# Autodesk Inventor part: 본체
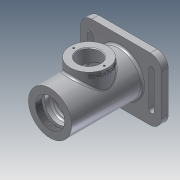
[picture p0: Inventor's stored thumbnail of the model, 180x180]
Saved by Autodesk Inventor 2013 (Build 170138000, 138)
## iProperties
Created: 2021-07
Part Number: 본체
Material: 알루미늄 6061
Document SubType Name: Modeling
Designer: user
Density: 2.71 g/cm^3
Mass: 738.277 g
Surface Area: 645 cm^2
Volume: 272.427 cm^3
Author: user
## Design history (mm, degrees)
sketch "스케치1"
  geometry: C1 r 31 at (0, 0); 1 further point
  constraints: 1 centre point, 1 coincident
  dimensions: "d0" = 62 diameter of C1
extrude "돌출1" new body sketch "스케치1" distance "d1" = 115; taper "d2" = 0 deg
node "작업 평면1"
sketch "스케치2"
  geometry: L1 (-58, 45)-(58, 45); L2 (58, 45)-(58, -45); L3 (58, -45)-(-58, -45); L4 (-58, -45)-(-58, 45); L5 (-58, 45)-(58, -45); L6 (58, 45)-(-58, -45); 1 further point
  constraints: 12 end point, 2 midpoint, 2 parallel, 1 horizontal, 1 perpendicular
  dimensions: "d4" = 116 distance of L2.end L3.end; "d5" = 90 distance of L1.end L2.end
extrude "돌출2" join sketch "스케치2" distance "d6" = 10; taper "d7" = 0 deg
sketch "스케치3"
  geometry: C1 r 31 at (0, 0) reference; C2 r 35 at (0, 0)
  constraints: 1 centre point, 1 coincident
  dimensions: "d8" = 70 diameter of C2
extrude "돌출3" join sketch "스케치3" distance "d9" = 3; taper "d10" = 0 deg
node "작업 평면2"
sketch "스케치5"
  geometry: L1 (31, 115)-(-31, 115) reference; L2 (35, 0)-(-35, 0) reference; L3 (0, 115)-(0, 0); L4 (21, 115)-(21, 106); L5 (21, 106)-(24, 106); L6 (24, 106)-(24, 103); L7 (24, 103)-(20, 103); L8 (20, 103)-(20, 94); L9 (20, 94)-(17.5, 94); L10 (17.5, 94)-(17.5, 90.75); L11 (17.5, 90.75)-(18.5, 90.75); L12 (18.5, 90.75)-(18.5, 89); L13 (18.5, 89)-(17.5, 89); L14 (17.5, 89)-(17.5, 78); L15 (17.5, 78)-(26, 78); L16 (26, 78)-(26, 40); L17 (26, 40)-(17.5, 40); L18 (17.5, 40)-(17.5, 29); L19 (17.5, 29)-(16, 29); L20 (16, 29)-(16, 24); L21 (16, 24)-(10, 24); L22 (10, 24)-(10, 21.3); L23 (10, 21.3)-(12.5, 21.3); L24 (12.5, 21.3)-(12.5, 14); L25 (12.5, 14)-(16, 14); L26 (16, 14)-(22, 0)
  constraints: 48 end point, 12 perpendicular, 11 parallel, 2 point on line, 1 midpoint
  dimensions: "d12" = 42 diameter of L4 L3; "d14" = 40 diameter of L8 L3; "d15" = 48 diameter of L6 L3; "d16" = 37 diameter of L12 L3; "d17" = 35 diameter of L14 L3; "d18" = 52 diameter of L16 L3; "d19" = 35 diameter of L18 L3; "d20" = 1.75 distance of L11.end L12.end; "d21" = 32 diameter of L20 L3; "d22" = 20 diameter of L22 L3; "d23" = 25 diameter of L24 L3; "d24" = 44 diameter of L26.end L3; "d25" = 12 distance between parallel lines of L7 L1; "d27" = 21 distance between parallel lines of L9 L1; "d28" = 35 diameter of L10 L3; "d29" = 14 distance from line of L25 L26.end; "d35" = 24 distance between parallel lines of L21 L2; "d36" = 7.3 distance of L23.end L24.end; "d50" = 65 distance between parallel lines of L19 L9; "d51" = 11 distance of L17.end L18.end; "d52" = 3 distance of L5.end L6.end; "d53" = 38 distance of L15.end L16.end; "d55" = 32 diameter of L25.end L3; "d56" = 11 distance of L13.end L14.end
revolve "회전1" sketch "스케치5" stored, may be unused: angle "d38" = 90 deg
feature "스레드1" dims "d39" = 10, "d40" = 0
node "작업 평면3"
sketch "스케치6"
  geometry: L1 (31, 115)-(-31, 115) reference; C1 r 27 at (0, 59); 2 further points
  constraints: 1 centre point, 1 midpoint, 1 vertical alignment
  dimensions: "d42" = 54 diameter of C1; "d43" = 56 distance from line of C1.centre L1
extrude "돌출4" join sketch "스케치6" stored distance "d44" = 3; taper "d45" = 0 deg
sketch "스케치7"
  geometry: C1 r 27 at (0, 0) reference; C2 r 16 at (0, 0); 1 further point
  constraints: 1 centre point, 1 coincident
  dimensions: "d46" = 32 diameter of C2
extrude "돌출5" cut sketch "스케치7" stored distance "d47" = 3; taper "d48" = 0 deg
fillet "모깎기1" dims "d49" = 3
fillet "모깎기2" dims "d57" = 0.3
fillet "모깎기3" dims "d58" = 3
chamfer "모따기1" distance "d59" = 0.7; stored, may be unused: second distance "d60" = 2, angle "d61" = 30 deg
chamfer "모따기2" distance "d62" = 1; stored, may be unused: second distance "d63" = 2, angle "d64" = 30 deg
chamfer "모따기3" distance "d65" = 1; stored, may be unused: second distance "d66" = 2, angle "d67" = 30 deg
sketch "스케치8"
  geometry: C1 r 27 at (0, 0) reference; 2 further points
  constraints: 1 horizontal alignment
  dimensions: "d68" = 22 distance of point (-22, 0) C1.centre
hole "구멍1" sketch "스케치8" at (-22, 0) diameter "d69" = 2.459; stored, may be unused: countersink angle "d73" = 90 deg, drill point angle "d75" = 118 deg; dims "d70" = 6, "d71" = 4, "d72" = 2, "d74" = 8
fillet "모깎기4" dims "d79" = 16
sketch "스케치9" dims "d80" = 8, "d83" = 8
  geometry: L1 (40, 25)-(48, 25); L2 (48, 25)-(48, -25); L3 (48, -25)-(40, -25); L4 (40, -25)-(40, 25); C1 r 31 at (0, 0) reference; 3 further points
  constraints: 8 end point, 2 horizontal alignment, 2 parallel, 1 coincident, 1 horizontal, 1 midpoint, 1 perpendicular, 4 other
  dimensions: "d81" = 44 horizontal distance of point (44, 25) C1.centre; "d82" = 25 vertical distance of point (44, 25) C1.centre; "d84" = 44 horizontal distance of point (44, -25) C1.centre; "d85" = 25 vertical distance of point (44, -25) C1.centre
extrude "돌출6" cut sketch "스케치9" stored distance "d86" = 3; taper "d87" = 0 deg
node "작업 평면4"
sketch "스케치10"
  geometry: L1 (42, 86)-(42, 32) reference; L2 (31, 115)-(-31, 115) reference; 3 further points
  constraints: 1 horizontal alignment, 1 midpoint, 1 other
  dimensions: "d89" = 8 distance from line of point (34, 59) L1; "d91" = 56 distance from line of point (34, 59) L2 (derived)
feature "엠보싱1" sketch "스케치10" dims "d92" = 0.5, "d93" = 0
fillet "모깎기5" dims "d94" = 3
node "솔리드1"
pattern_circular "원형 패턴1" dims angle "d77" = 360 deg
mirror "대칭1"
other parameters: "d3" = -3, "d11" = 42, "d41" = 42
